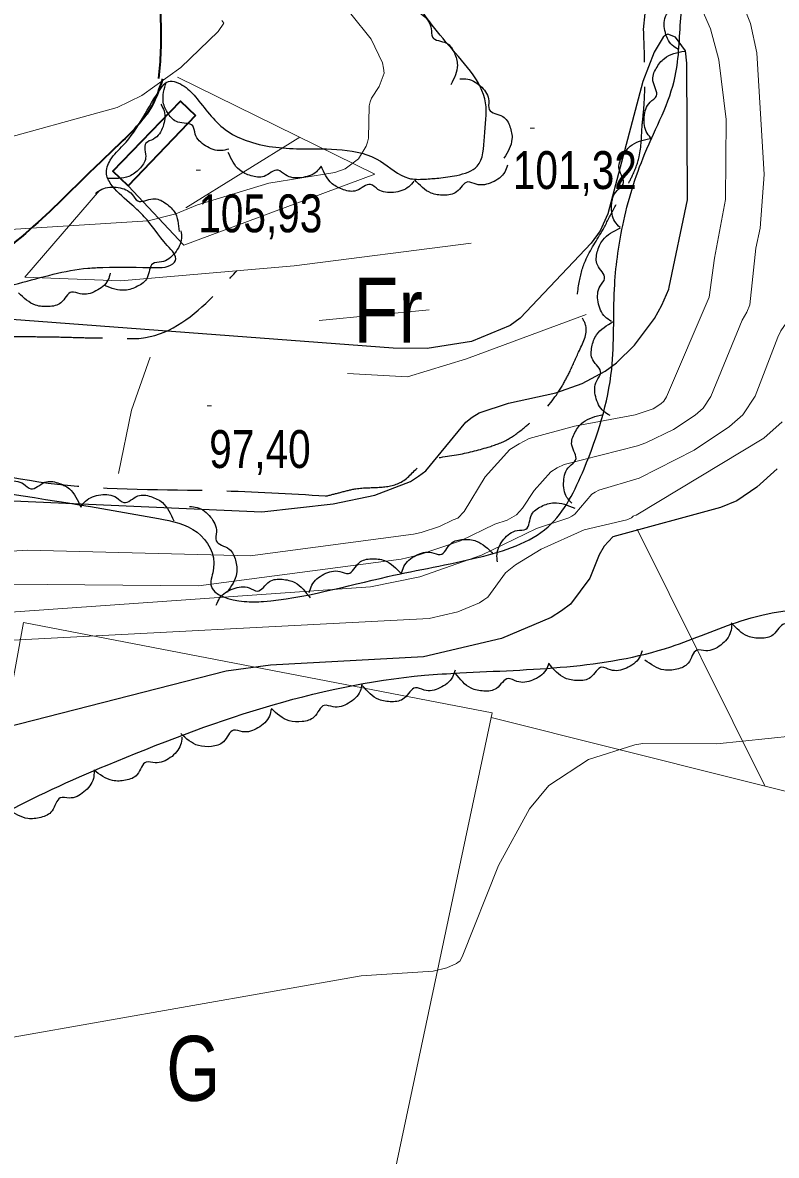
# Model space of a CAD drawing. Extents: x 483843 to 488449, y 4381269 to 4384483.
# Drawn here: x 486561.6 to 486735.6, y 4382813.6 to 4383075.2 of the extents above; entities that cross this region are included whole.
import ezdxf
from ezdxf.enums import TextEntityAlignment as Align

# ---------------------------------------------------------------- set-up
doc = ezdxf.new("R2010")
doc.units = 0
doc.header["$LTSCALE"] = 3.8
doc.linetypes.add('LONG_DASHED', pattern=[7.5, 6, -1.5])
for name, color, linetype, lineweight in [('25', 7, 'LONG_DASHED', 25), ('27', 7, 'Continuous', 25), ('47', 7, 'Continuous', 35), ('51', 7, 'Continuous', 13), ('6', 7, 'Continuous', 35), ('7', 7, 'Continuous', 13), ('8', 7, 'Continuous', 25), ('9', 7, 'Continuous', 13)]:
    doc.layers.add(name, color=color, linetype=linetype, lineweight=lineweight)
doc.layers.add('31', color=7, linetype='Continuous')

msp = doc.modelspace()

# ---------------------------------------------------------------- linework, layer by layer
at = {"layer": '25'}
msp.add_lwpolyline([(486704.92, 4383073.62), (486705.71, 4383081.56), (486704.16, 4383088.86), (486698.64, 4383095.92), (486687.91, 4383106.95), (486677.47, 4383111.38), (486664.49, 4383116.74), (486654.91, 4383123.56), (486649.09, 4383130.99), (486645.39, 4383140.13), (486641.95, 4383145.88), (486638.42, 4383151.26), (486632.51, 4383157.34), (486627.26, 4383162.75), (486622.95, 4383165.73), (486597.81, 4383181.1), (486597.01, 4383182.91), (486596.65, 4383184.2)], dxfattribs=at)
for points in [[(486631.49, 4382965.86), (486634.88, 4382966.72), (486638.49, 4382967.57), (486644.2, 4382967.93), (486649.25, 4382969.29), (486653.73, 4382973.2), (486661.72, 4382975.41), (486669.02, 4382977.18), (486673.62, 4382978.99), (486677.57, 4382981.86), (486680.53, 4382984.3), (486685.95, 4382991.05), (486687.8, 4382994.47), (486689.9, 4382999.09), (486691.56, 4383005.22), (486690.25, 4383008.09), (486689.97, 4383014.85), (486691.47, 4383020.23), (486695.55, 4383027.45), (486697.95, 4383032.07), (486700.64, 4383036.68), (486702.26, 4383039.74), (486703.9, 4383044.22), (486704.6, 4383051.56), (486704.96, 4383055.23), (486705.2, 4383062.06), (486704.92, 4383073.62)], [(486631.49, 4382965.86), (486606.6, 4382967.05), (486569.62, 4382968.55), (486534.88, 4382973.33), (486524.4, 4382975.28), (486520.19, 4382979.92), (486520.65, 4382991.46), (486521.72, 4382998.05), (486524.79, 4383002.81), (486534.71, 4383003.42), (486540.55, 4383002.96), (486550.46, 4383002.89), (486559.08, 4383002.77), (486564.11, 4383002.7), (486570.79, 4383002.6), (486576.34, 4383002.45), (486581.74, 4383002.37), (486589.92, 4383002.48), (486605.51, 4383012.01), (486610.98, 4383017.9)]]:
    msp.add_spline(points, degree=3, dxfattribs=at)
at = {"layer": '27'}
for points in [[(486510.56, 4382972.83), (486592.89, 4382960.7), (486601.82, 4382957.51), (486605.65, 4382949.21), (486605.01, 4382945.38), (486612.67, 4382941.55), (486617.14, 4382941.55), (486645.86, 4382947.29), (486666.92, 4382951.76), (486682.87, 4382958.79), (486691.17, 4382972.2), (486697.55, 4382995.18), (486698.19, 4383013.7), (486700.1, 4383028.38), (486705.21, 4383044.98), (486712.23, 4383062.86), (486713.51, 4383076.27), (486713.51, 4383089.04), (486710.95, 4383094.79), (486707.76, 4383100.53), (486695, 4383117.13), (486669.47, 4383126.71), (486659.9, 4383138.2), (486650.96, 4383150.33), (486637.56, 4383166.93), (486626.71, 4383177.15), (486626.71, 4383182.26), (486685.43, 4383205.88), (486717.33, 4383225.68), (486728.82, 4383230.78), (486732.65, 4383230.78), (486739.03, 4383228.87), (486743.5, 4383227.59), (486748.61, 4383221.21), (486745.41, 4383218.01), (486738.39, 4383203.97), (486732.65, 4383177.15), (486727.55, 4383157.36), (486725.63, 4383141.39), (486727.55, 4383133.73), (486765.2, 4383119.05), (486811.79, 4383105), (486813.06, 4383104.36), (486819.44, 4383106.92), (486824.55, 4383113.3), (486825.19, 4383127.35), (486820.08, 4383159.91), (486816.89, 4383173.96), (486816.89, 4383178.43), (486819.44, 4383183.54), (486826.46, 4383182.9), (486839.23, 4383173.96), (486851.35, 4383158.63), (486851.35, 4383155.44), (486854.55, 4383149.7), (486860.29, 4383146.5), (486874.33, 4383147.78), (486881.35, 4383147.78), (486885.18, 4383146.5), (486885.82, 4383140.12), (486878.16, 4383135.65), (486855.18, 4383117.77), (486850.08, 4383106.92), (486844.33, 4383092.87), (486846.25, 4383073.72), (486850.08, 4383059.67), (486853.27, 4383048.81), (486859.01, 4383039.24), (486866.03, 4383030.3), (486874.97, 4383020.08), (486875.61, 4383011.78), (486873.05, 4382997.74), (486873.05, 4382979.86), (486877.52, 4382957.51), (486880.71, 4382931.33), (486896.03, 4382901.96), (486916.45, 4382878.98), (486920.28, 4382878.34), (486934.96, 4382878.98), (486953.46, 4382889.19), (486954.74, 4382904.52), (486949.64, 4382917.29), (486943.25, 4382926.22), (486931.13, 4382935.16), (486926.66, 4382940.27), (486927.94, 4382947.29), (486935.6, 4382954.32), (486935.6, 4382959.43), (486931.77, 4382975.39), (486917.73, 4383017.53), (486919, 4383028.38)], [(486517.12, 4382975.46), (486478.87, 4382976.46), (486461.53, 4382976.33), (486451.25, 4382976.18), (486439.08, 4382975.37), (486432.08, 4382973.37), (486426.88, 4382972.32), (486418.36, 4382969.44), (486413.52, 4382966.81), (486407.62, 4382963.07), (486396.4, 4382955.5), (486391.57, 4382953.32), (486373.31, 4382951.18), (486352.48, 4382948.33), (486347.06, 4382947.35), (486336.84, 4382945.85), (486333.37, 4382944.62), (486327.79, 4382943.05), (486327.57, 4382943.13), (486330.01, 4382956.45), (486336.39, 4382967.39), (486336.97, 4382971.21), (486337.3, 4382972.93), (486339.42, 4382979.43), (486364.33, 4382984.7), (486392.61, 4382989.55), (486423.95, 4382997.95), (486432.35, 4382997.98), (486439.93, 4382998.02), (486449.54, 4382998.04), (486459.3, 4382998.27), (486474.7, 4382999.48), (486495, 4383002.26), (486504.46, 4383003.25), (486521.76, 4383006.08), (486527.57, 4383007.87), (486540.54, 4383012.19), (486550.15, 4383012.88), (486560.61, 4383014.98), (486576.64, 4383018.5), (486580.1, 4383018.68), (486592.33, 4383018.65), (486595.18, 4383018.99), (486596.85, 4383020.31), (486594.95, 4383023.72), (486589.65, 4383030.4), (486586.83, 4383033.06), (486582.24, 4383037.56), (486580.93, 4383040.2), (486581.8, 4383043.49), (486584.78, 4383046.9), (486593.6, 4383060.2), (486594.82, 4383061.46), (486598.41, 4383060.81), (486601.45, 4383058.07), (486608.32, 4383050.54), (486613.16, 4383047.99), (486625.59, 4383046.09), (486644.16, 4383043.2), (486650.63, 4383039.28), (486654.38, 4383039.07), (486657.61, 4383039.33), (486661.82, 4383039.94), (486666.5, 4383042.05), (486668.17, 4383048.86), (486668.43, 4383056.66), (486659.26, 4383070.74), (486654.39, 4383076.97), (486650.74, 4383083.55), (486649, 4383088.22), (486644.49, 4383092.64), (486637.44, 4383098.52), (486637.21, 4383098.07), (486635.3, 4383100.73), (486626.82, 4383106.18), (486619.13, 4383108.76), (486613.5, 4383108.84), (486603.45, 4383108.61), (486595.87, 4383108.64), (486590.24, 4383108.88), (486588.69, 4383110.7), (486583.56, 4383118.73), (486577.45, 4383127.07), (486575.97, 4383128.81), (486571.61, 4383138.56), (486572.25, 4383141.4), (486573.29, 4383150.84), (486572.89, 4383154.52), (486572.03, 4383157.08), (486570.51, 4383161.08), (486566.59, 4383165.19)], [(486713, 4383068.99), (486711.54, 4383069.99), (486709.83, 4383073.38), (486710.2, 4383077.06), (486711.19, 4383078.85), (486709.43, 4383081.94), (486709.34, 4383084.92), (486710.52, 4383087.71), (486714.52, 4383090.64)], [(486648.88, 4383078.47), (486650.66, 4383078.52), (486654.03, 4383076.86), (486655.89, 4383073.82), (486656.15, 4383071.87), (486659.39, 4383070.48), (486661.22, 4383068.22), (486661.92, 4383065.41), (486660.41, 4383060.88)], [(486706.85, 4383048.31), (486705.73, 4383049.69), (486705.04, 4383053.42), (486706.42, 4383056.84), (486707.88, 4383058.28), (486707.06, 4383061.74), (486707.81, 4383064.63), (486709.72, 4383066.97), (486714.38, 4383068.66)], [(486609.14, 4383046), (486607.39, 4383045.66), (486603.78, 4383046.77), (486601.41, 4383049.48), (486600.83, 4383051.37), (486597.39, 4383052.24), (486595.2, 4383054.17), (486594.03, 4383056.84), (486594.76, 4383061.54)], [(486662.52, 4383062.25), (486664.3, 4383062.17), (486667.54, 4383060.29), (486669.16, 4383057.12), (486669.27, 4383055.16), (486672.4, 4383053.54), (486674.06, 4383051.17), (486674.53, 4383048.32), (486672.68, 4383043.9)], [(486593.44, 4383056.36), (486594.2, 4383054.82), (486593.96, 4383051.21), (486591.78, 4383048.34), (486590.01, 4383047.35), (486589.95, 4383043.95), (486588.52, 4383041.44), (486586.1, 4383039.71), (486581.16, 4383039.23)], [(486699.47, 4383027.92), (486698.3, 4383029.26), (486697.51, 4383032.97), (486698.79, 4383036.43), (486700.21, 4383037.92), (486699.28, 4383041.35), (486699.95, 4383044.26), (486701.79, 4383046.66), (486706.4, 4383048.49)], [(486630.48, 4383042.09), (486629.36, 4383040.77), (486625.84, 4383039.41), (486622.21, 4383040.05), (486620.51, 4383041.14), (486617.28, 4383039.7), (486614.3, 4383039.85), (486611.62, 4383041.19), (486609.04, 4383045.24)], [(486651.88, 4383038.62), (486650.73, 4383037.32), (486647.2, 4383036.01), (486643.58, 4383036.7), (486641.89, 4383037.82), (486638.64, 4383036.43), (486635.66, 4383036.62), (486633.01, 4383038.01), (486630.48, 4383042.09)], [(486673.5, 4383042.27), (486672.86, 4383040.69), (486669.95, 4383038.35), (486666.29, 4383037.89), (486664.32, 4383038.42), (486661.72, 4383036.11), (486658.83, 4383035.36), (486655.85, 4383035.85), (486652.08, 4383038.93)], [(486578.35, 4383035.78), (486579.83, 4383036.74), (486583.6, 4383037.13), (486586.85, 4383035.54), (486588.12, 4383034.03), (486591.64, 4383034.55), (486594.42, 4383033.62), (486596.53, 4383031.6), (486597.7, 4383027.01)], [(486598.11, 4383027.14), (486598.23, 4383025.42), (486596.67, 4383022.01), (486593.61, 4383019.95), (486591.61, 4383019.53), (486590.31, 4383016.28), (486588.07, 4383014.32), (486585.2, 4383013.41), (486580.48, 4383014.49)], [(486697.47, 4383006.22), (486696.03, 4383007.27), (486694.42, 4383010.7), (486694.88, 4383014.36), (486695.92, 4383016.13), (486694.24, 4383019.26), (486694.23, 4383022.25), (486695.48, 4383025), (486699.56, 4383027.82)], [(486581.8, 4383017.36), (486581.25, 4383015.74), (486578.48, 4383013.24), (486574.86, 4383012.58), (486572.85, 4383013), (486570.4, 4383010.54), (486567.56, 4383009.64), (486564.56, 4383009.96), (486560.61, 4383012.83)], [(486697.16, 4382984.51), (486695.67, 4382985.46), (486693.85, 4382988.79), (486694.09, 4382992.47), (486695.03, 4382994.3), (486693.17, 4382997.33), (486692.97, 4383000.31), (486694.06, 4383003.13), (486697.96, 4383006.19)], [(486688.37, 4382964.21), (486687.22, 4382965.57), (486686.47, 4382969.29), (486687.8, 4382972.73), (486689.23, 4382974.2), (486688.35, 4382977.65), (486689.05, 4382980.55), (486690.93, 4382982.92), (486695.56, 4382984.69)], [(486553.5, 4382966.5), (486554.61, 4382967.89), (486558.12, 4382969.33), (486561.75, 4382968.68), (486563.47, 4382967.55), (486566.68, 4382969.07), (486569.66, 4382968.93), (486572.35, 4382967.55), (486574.96, 4382963.33)], [(486574.96, 4382963.34), (486576.08, 4382964.72), (486579.59, 4382966.17), (486583.22, 4382965.52), (486584.93, 4382964.39), (486588.15, 4382965.91), (486591.13, 4382965.77), (486593.82, 4382964.38), (486596.43, 4382960.17)], [(486600.07, 4382963.47), (486601.84, 4382963.25), (486604.92, 4382961.04), (486606.3, 4382957.62), (486606.24, 4382955.57), (486609.23, 4382953.64), (486610.7, 4382951.04), (486610.94, 4382948.03), (486608.75, 4382943.58)], [(486671.2, 4382950.67), (486671.07, 4382952.44), (486672.63, 4382955.9), (486675.73, 4382957.92), (486677.75, 4382958.26), (486679.06, 4382961.57), (486681.32, 4382963.51), (486684.23, 4382964.34), (486689.02, 4382963.06)], [(486649, 4382947.91), (486649.56, 4382949.59), (486652.34, 4382952.17), (486655.97, 4382952.84), (486657.97, 4382952.38), (486660.45, 4382954.93), (486663.29, 4382955.85), (486666.29, 4382955.49), (486670.22, 4382952.46)], [(486627.73, 4382943.62), (486628.31, 4382945.29), (486631.12, 4382947.84), (486634.76, 4382948.47), (486636.75, 4382947.98), (486639.26, 4382950.5), (486642.11, 4382951.39), (486645.11, 4382950.99), (486649, 4382947.92)], [(486606.26, 4382940.7), (486607.04, 4382942.3), (486610.14, 4382944.49), (486613.83, 4382944.66), (486615.75, 4382943.94), (486618.55, 4382946.13), (486621.49, 4382946.66), (486624.41, 4382945.91), (486627.9, 4382942.38)], [(486286.37, 4382818.73), (486339.99, 4382829.8), (486391.37, 4382851.5), (486440.09, 4382863.84), (486483.65, 4382864.6), (486530.94, 4382876.91), (486556.13, 4382891.91), (486581.09, 4382903.76), (486654.31, 4382924.49), (486662.47, 4382925.04), (486711.17, 4382931.08), (486727.4, 4382937.04), (486766.91, 4382937.87), (486808.31, 4382909.18), (486821.81, 4382880.51), (486820.67, 4382841.64), (486812.49, 4382812.89), (486799.42, 4382770.69), (486791.78, 4382745.03), (486785, 4382714.29), (486784.58, 4382691.25), (486792.33, 4382675.66), (486812.73, 4382668.89), (486834.8, 4382649.92), (486842.09, 4382627.43), (486847.24, 4382607.13), (486841.07, 4382582.93), (486840.3, 4382544.36), (486820.33, 4382480.87), (486817.63, 4382459.06), (486815.97, 4382420.47), (486812.52, 4382387.85), (486799.99, 4382362.84), (486771.04, 4382337.85), (486733.51, 4382314.2), (486712.72, 4382296.59), (486687.38, 4382263.88), (486690.96, 4382229.15), (486713.22, 4382200.82), (486764.33, 4382192.43), (486778.5, 4382149.68), (486779.01, 4382117.89), (486787.15, 4382072.98), (486813.93, 4382065.66), (486857.54, 4382071.08), (486866.35, 4382080.34), (486893.23, 4382096.95), (486915.85, 4382116.25), (486928.06, 4382127.9), (486936.43, 4382157.7), (486928.1, 4382176.05), (486914.22, 4382205.24), (486902.98, 4382218.81), (486885.61, 4382249.79), (486879.29, 4382279.36), (486884.99, 4382315.26), (486888.52, 4382343.76), (486907.35, 4382375.88), (486922.54, 4382388.35), (486945.58, 4382366.33), (486954.28, 4382323.31), (486963.51, 4382283.6), (486982.52, 4382253.24), (487009.26, 4382225.98), (487037.6, 4382230.32), (487058.96, 4382252.37), (487069.68, 4382284.84), (487065.95, 4382338.17), (487054.24, 4382363.72), (487038.01, 4382386.56), (487027.59, 4382400.37), (487012.06, 4382422.24), (486991.9, 4382450.1), (486977.88, 4382471.56), (486976.21, 4382486.9), (486980.43, 4382521.64), (487024.88, 4382562.69), (487055.81, 4382565.06), (487106.74, 4382596.8), (487155.96, 4382614.11), (487207.74, 4382666.72), (487232.21, 4382676.6), (487267.31, 4382683.94), (487282.71, 4382693.48), (487294.56, 4382707.98), (487340.16, 4382736.84), (487389.67, 4382736.07), (487421.36, 4382716.33), (487454.29, 4382680.57), (487455.44, 4382629.06), (487501.37, 4382598.97)], [(486746.5, 4382940.54), (486745.89, 4382938.88), (486743.04, 4382936.38), (486739.39, 4382935.82), (486737.4, 4382936.34), (486734.85, 4382933.87), (486731.98, 4382933.04), (486728.99, 4382933.49), (486725.16, 4382936.64)], [(486725.25, 4382936.27), (486725.01, 4382934.52), (486722.73, 4382931.48), (486719.28, 4382930.17), (486717.23, 4382930.27), (486715.24, 4382927.32), (486712.61, 4382925.91), (486709.59, 4382925.72), (486705.19, 4382928.01)], [(486704.57, 4382930.16), (486703.89, 4382928.52), (486700.93, 4382926.14), (486697.26, 4382925.74), (486695.3, 4382926.35), (486692.64, 4382923.99), (486689.74, 4382923.28), (486686.77, 4382923.85), (486683.08, 4382927.16)], [(486683.07, 4382927.27), (486682.34, 4382925.65), (486679.3, 4382923.37), (486675.62, 4382923.08), (486673.68, 4382923.75), (486670.95, 4382921.47), (486668.03, 4382920.85), (486665.08, 4382921.52), (486661.49, 4382924.94)], [(486661.4, 4382925.69), (486660.77, 4382924.03), (486657.88, 4382921.57), (486654.22, 4382921.07), (486652.25, 4382921.62), (486649.65, 4382919.18), (486646.78, 4382918.39), (486643.79, 4382918.88), (486640.01, 4382922.08)], [(486639.91, 4382922.51), (486639.45, 4382920.8), (486636.81, 4382918.07), (486633.23, 4382917.2), (486631.2, 4382917.55), (486628.87, 4382914.87), (486626.08, 4382913.79), (486623.07, 4382913.98), (486618.98, 4382916.79)], [(486618.98, 4382916.78), (486618.52, 4382915.07), (486615.88, 4382912.34), (486612.3, 4382911.47), (486610.27, 4382911.82), (486607.94, 4382909.14), (486605.15, 4382908.06), (486602.14, 4382908.25), (486598.05, 4382911.06)], [(486598.33, 4382910.18), (486598.02, 4382908.43), (486595.65, 4382905.47), (486592.15, 4382904.29), (486590.1, 4382904.46), (486588.01, 4382901.58), (486585.34, 4382900.26), (486582.31, 4382900.18), (486577.99, 4382902.62)], [(486578.08, 4382902.41), (486577.88, 4382900.65), (486575.7, 4382897.54), (486572.29, 4382896.14), (486570.23, 4382896.17), (486568.34, 4382893.16), (486565.75, 4382891.68), (486562.74, 4382891.4), (486558.27, 4382893.55)]]:
    msp.add_spline(points, degree=3, dxfattribs=at)
at = {"layer": '47'}
msp.add_line((486601.44, 4383053.77), (486585.92, 4383037.5), dxfattribs=at)
msp.add_lwpolyline([(486585.92, 4383037.5), (486582.37, 4383040.93), (486598, 4383057.11), (486601.44, 4383053.76)], dxfattribs=at)
at = {"layer": '51'}
for p, q in [((486599.2, 4383032.43), (486625.52, 4383048.75)), ((486562.06, 4383016.46), (486579.3, 4383036.47)), ((486630.05, 4383006.41), (486655.44, 4383008.89)), ((486703.4, 4382958.22), (486732.89, 4382898.94))]:
    msp.add_line(p, q, dxfattribs=at)
for points in [[(486597.31, 4383062.63), (486642.84, 4383040.21), (486598.78, 4383023.81), (486585.92, 4383037.5)], [(486562.06, 4383016.46), (486584.11, 4383015.62), (486624.22, 4383019.02), (486665.12, 4383024.29)], [(486669.72, 4382914.77), (486812.46, 4382878.97), (486872.99, 4382868.23), (486875.9, 4382865.44), (486849.95, 4383012.66)], [(486691.67, 4383007.85), (486663.99, 4382997.59), (486650.42, 4382993.43), (486636.55, 4382994.16)], [(486583.69, 4382971.13), (486586.68, 4382985.72), (486590.98, 4382997.96)], [(486269.04, 4382276.51), (486282.76, 4382298.7), (486279.91, 4382306.15), (486475.97, 4382417.35), (486565.92, 4382470.15), (486593.59, 4382581.58), (486631.16, 4382732.98), (486669.94, 4382915.82), (486561.72, 4382936.66), (486535.7, 4382792.93), (486414.87, 4382771.51)]]:
    msp.add_lwpolyline(points, dxfattribs=at)
at = {"layer": '6'}
for points in [[(486616.4, 4383398.76), (486609.53, 4383398.32), (486605.76, 4383397.51), (486603.64, 4383396.68), (486601.06, 4383394.53), (486581.77, 4383363.75), (486567.92, 4383345.34), (486555.49, 4383325.84), (486547.31, 4383311.93), (486544.63, 4383297.26), (486542.93, 4383288.69), (486537.77, 4383273.81), (486528.83, 4383256.87), (486521.61, 4383244.78), (486506.85, 4383225.48), (486495.82, 4383205.81), (486490.76, 4383183.12), (486490.75, 4383171.7), (486494.48, 4383158.89), (486500.87, 4383143.53), (486507.02, 4383132), (486513.34, 4383122.31), (486520.6, 4383114.98), (486524.69, 4383110.49), (486524.72, 4383107.37), (486523.98, 4383102.8), (486520.48, 4383093.44), (486518.01, 4383088.42), (486514.34, 4383083.16), (486511.09, 4383077.17), (486509.02, 4383072.98), (486506.76, 4383070.57), (486504.86, 4383068.89), (486504.98, 4383068.05), (486506.45, 4383067.29), (486509.87, 4383067.88), (486515.23, 4383069.39), (486530.79, 4383072.38), (486552.79, 4383077.34), (486574.89, 4383083.42), (486585.15, 4383087.17), (486588.99, 4383088.06), (486590.1, 4383087.94), (486592.93, 4383085.95), (486593.37, 4383080.97), (486593.38, 4383076.71), (486593.42, 4383068.62), (486592.95, 4383062.34)], [(486593.85, 4383062.23), (486591.36, 4383055.96), (486583.58, 4383046.92), (486572.39, 4383036.05), (486557.19, 4383022.53), (486539.86, 4383012.5), (486525.54, 4383007.75), (486520.42, 4383006.25), (486519.2, 4383000.04), (486518.39, 4382990.6), (486517.24, 4382979.78)]]:
    msp.add_spline(points, degree=3, dxfattribs=at)
at = {"layer": '7'}
for p, q in [((486678.73, 4383050.87), (486679.73, 4383050.87)), ((486601.61, 4383041.17), (486602.61, 4383041.17)), ((486604.13, 4382986.73), (486605.13, 4382986.73))]:
    msp.add_line(p, q, dxfattribs=at)
at = {"layer": '8'}
for points in [[(486503.67, 4382967.23), (486616.81, 4382962.27), (486633.21, 4382964.1), (486642.87, 4382966.11), (486651.08, 4382969.27), (486652.96, 4382970.44), (486654.67, 4382971.74), (486663.86, 4382982.97), (486665.35, 4382984.12), (486666.97, 4382985.11), (486673.76, 4382987.32), (486684.62, 4382989.71), (486690.7, 4382991.89), (486696.03, 4382994.73), (486698.66, 4382996.64), (486702.82, 4383000.73), (486707.45, 4383006.87), (486709.12, 4383009.94), (486710.73, 4383013.65), (486710.78, 4383014.12), (486715.07, 4383034.29), (486714.89, 4383065.86), (486714.62, 4383068.67), (486712.27, 4383071.84), (486710.52, 4383072.58), (486710, 4383072.31), (486709.45, 4383071.83), (486707.34, 4383068.37), (486704.73, 4383061.6), (486696.63, 4383031.05), (486694.91, 4383027.15), (486692.8, 4383024.31), (486676.42, 4383006.99), (486674.07, 4383005.24), (486665.16, 4383001.58), (486654.91, 4382999.98), (486647.12, 4383000.06)], [(486647.12, 4383000.06), (486500.67, 4383011.02), (486471.59, 4383005.42), (486446.36, 4383004.47), (486399.72, 4382996.84), (486397.23, 4382996.12), (486383.47, 4382989.8), (486378.07, 4382988.35), (486334.25, 4382981.63), (486250.77, 4382985.2), (486205.67, 4382993.71)], [(486735.77, 4382972.16), (486731.07, 4382967.96), (486726.47, 4382964.79), (486722.7, 4382963.22), (486697.82, 4382956.43), (486695.83, 4382954.35), (486694.67, 4382952.29), (486692.49, 4382946.93), (486688, 4382940.88), (486685.96, 4382939.34), (486683.57, 4382937.85), (486672.07, 4382932.96), (486654.08, 4382928.74), (486618.74, 4382926.85), (486608.51, 4382925.41), (486557.74, 4382912.44)]]:
    msp.add_lwpolyline(points, dxfattribs=at)
at = {"layer": '9'}
for points in [[(486558.44, 4382945.54), (486602.16, 4382945.13), (486648.95, 4382951.32), (486652.86, 4382952.21), (486662.66, 4382955.54), (486670.55, 4382959.38), (486673.42, 4382960.31), (486675.59, 4382961.57), (486676.94, 4382963.06), (486679.62, 4382967.17), (486683.51, 4382971.46), (486684.96, 4382972.38), (486686.57, 4382973.2), (486703.49, 4382977.5), (486705.42, 4382978.19), (486711.85, 4382981.26), (486716.82, 4382984.56), (486718.68, 4382986.21), (486720.43, 4382988.87), (486727.69, 4383006.51), (486728.78, 4383008.37), (486729.43, 4383010.03), (486730.83, 4383023.16), (486731.8, 4383027.74), (486732.74, 4383040.13), (486731.04, 4383068.24), (486729.57, 4383074.98), (486725.69, 4383084.87)], [(486715.13, 4383085.83), (486720.37, 4383073.77), (486722.29, 4383066.63), (486723.99, 4383052.86), (486723.83, 4383034.38), (486721.31, 4383020.81), (486720.08, 4383011.84), (486710.2, 4382988.77), (486709.57, 4382987.81), (486708.89, 4382987.21), (486707.09, 4382986.01)], [(486607.57, 4383075.67), (486608.03, 4383075.09), (486606.73, 4383073.16), (486598.08, 4383064.87), (486589.09, 4383058.42), (486583.4, 4383055.65), (486493.07, 4383030.68), (486369.97, 4383010.4), (486324.1, 4383010.67), (486210.45, 4383025.25)], [(486552.41, 4383027.02), (486590.56, 4383029.41), (486596.93, 4383031.08), (486601.94, 4383033.15), (486618.41, 4383038.13), (486633.63, 4383040.58), (486635.98, 4383041.47), (486639.08, 4383043.74), (486640.9, 4383046.69), (486641.21, 4383047.6), (486641.43, 4383048.55), (486641.58, 4383055.99), (486641.79, 4383056.9), (486642.09, 4383057.76), (486643.88, 4383060.45), (486645.01, 4383063.57), (486644.9, 4383064.69), (486644.61, 4383065.93), (486642.01, 4383071.37), (486637.31, 4383077.24)], [(486556.59, 4382938.94), (486641.9, 4382944.92), (486653.23, 4382947.24), (486667.51, 4382952.2), (486680.17, 4382958.36), (486687.68, 4382960.82), (486688.37, 4382961.24), (486689, 4382961.72), (486692.95, 4382966.31), (486693.73, 4382966.81), (486694.6, 4382967.25), (486703.92, 4382969.98), (486716.62, 4382976.51), (486724.74, 4382981.92), (486727.79, 4382984.62), (486730.65, 4382988.96), (486735.87, 4383002.58), (486736.63, 4383004.02), (486737.84, 4383005.81), (486738.78, 4383008.22), (486741.36, 4383034.57), (486739.79, 4383069.85), (486738.78, 4383076.18)], [(486707.09, 4382986.01), (486702.99, 4382984.63), (486688.99, 4382982.05), (486678.53, 4382979.14), (486676.18, 4382977.95), (486674.06, 4382976.6), (486668.37, 4382970.33), (486663.51, 4382962.32), (486662.06, 4382960.77), (486660.92, 4382960.4), (486657.81, 4382958.89), (486653.56, 4382957.47), (486651.78, 4382957.05), (486614.12, 4382952.08), (486562.6, 4382953.37), (486506.87, 4382949.77), (486490.28, 4382947.07), (486439.04, 4382930.03), (486350.05, 4382913.74), (486340.11, 4382912.1), (486241.96, 4382913.04), (486233.39, 4382914.09), (486204.04, 4382922.07)], [(486554.73, 4382932.34), (486655.37, 4382937.58), (486662.02, 4382939.12), (486667, 4382941.24), (486668.04, 4382941.89), (486668.92, 4382942.56), (486673.06, 4382948.16), (486675.32, 4382949.99), (486681.3, 4382953.59), (486691.17, 4382958.06), (486701.06, 4382960.39), (486702.1, 4382960.84), (486702.4, 4382961.17), (486702.51, 4382961.24), (486702.63, 4382961.3), (486703.17, 4382961.45), (486732.67, 4382979.27), (486736.9, 4382983.02)], [(486751.48, 4382911.76), (486721.83, 4382908.68), (486704.74, 4382908.74), (486702.88, 4382908.4), (486692.19, 4382905.06), (486683.07, 4382899.01), (486678.57, 4382893.69), (486671.42, 4382880.54), (486663.06, 4382859.51), (486662.49, 4382858.49), (486662.14, 4382858.21), (486661.71, 4382857.93), (486659.46, 4382856.94), (486656.33, 4382856.18), (486639.7, 4382855.07), (486539.18, 4382837.35)]]:
    msp.add_lwpolyline(points, dxfattribs=at)

# ---------------------------------------------------------------- texts
at = {"layer": '31'}
for s, width, p in [('Fr', 0.85, (486645.94, 4383001.31)), ('G', 0.8, (486600.96, 4382826.22))]:
    msp.add_text(s, height=15, dxfattribs=dict(at, width=width)).set_placement(p, align=Align.CENTER)
at = {"layer": '7', "width": 0.8}
for s, p in [('101,32', (486674.73, 4383036.79)), ('105,93', (486602.11, 4383026.8)), ('97,40', (486604.63, 4382972.36))]:
    msp.add_text(s, height=8.75, dxfattribs=at).set_placement(p)

doc.saveas('drawing.dxf')
